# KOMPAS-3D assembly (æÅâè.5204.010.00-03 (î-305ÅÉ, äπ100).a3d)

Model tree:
1. Плоскость XY
2. Плоскость ZX
3. Плоскость ZY
4. Ось X
5. Ось Y
6. Ось Z
7. Начало координат  (labels: Операция без истории:1; ␣0; ␣1␣1; ␣2␣2)

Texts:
  Линия-выноска #1
  Линия-выноска #2
  Линия-выноска #3
  Отклонения формы и база
  Марка координационной оси
  Марка/позиционное обозначение с линией-выноской
  Марка/позиционное обозначение на линии
  Марка/позиционное обозначение без линии-выноски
